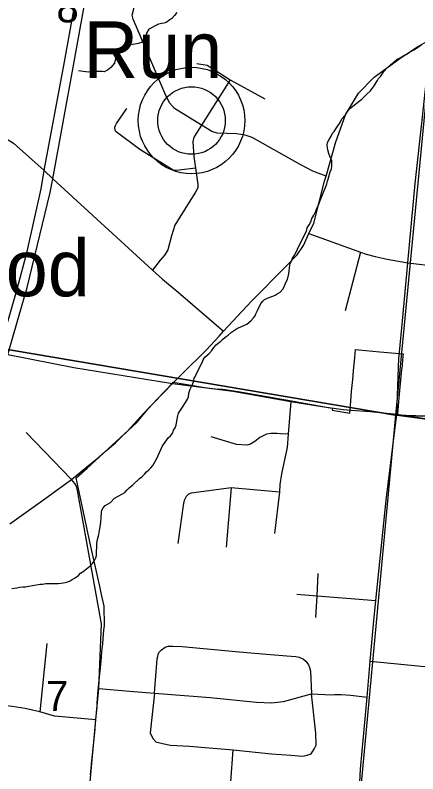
# Model space of a CAD drawing. Extents: x 0 to 34, y -3.9 to 26.2.
# Drawn here: x 7.442 to 8.005, y 17.265 to 18.325 of the extents above; entities that cross this region are included whole.
import ezdxf

# ---------------------------------------------------------------- set-up
doc = ezdxf.new("R2010")
doc.units = 0
for name, color, linetype in [('GM_X_City_Street', 7, 'Continuous'), ('GM_X_Corporation', 7, 'Continuous'), ('GM_X_County_Road', 7, 'Continuous'), ('GM_X_Interstate_Route', 7, 'Continuous'), ('GM_X_Minor_River', 7, 'Continuous'), ('GM_X_Section', 7, 'Continuous'), ('GM_X_Section_Text', 7, 'Continuous'), ('GM_X_State_Route', 7, 'Continuous'), ('GM_X_State_Shield', 7, 'Continuous'), ('GM_X_Township_Road', 7, 'Continuous'), ('GM_X_Unincorporated', 7, 'Continuous'), ('GM_X_Unincorporated_Location', 7, 'Continuous'), ('GM_X_Unincorporated_Text', 7, 'Continuous'), ('GM_X_US_Route', 7, 'Continuous')]:
    doc.layers.add(name, color=color, linetype=linetype)

msp = doc.modelspace()

# ---------------------------------------------------------------- linework, layer by layer
at = {"layer": 'GM_X_City_Street'}
msp.add_line((7.7437, 17.6648), (7.7369, 17.5816), dxfattribs=at)
for points in [[(7.827, 17.7854), (7.8234, 17.7394), (7.822, 17.7211), (7.8174, 17.6995), (7.814, 17.6842), (7.8119, 17.6693), (7.8113, 17.6586), (7.8045, 17.6009)], [(7.8234, 17.7394), (7.8129, 17.74), (7.8078, 17.7404), (7.7994, 17.7406), (7.7934, 17.7396), (7.7839, 17.7351), (7.777, 17.7295), (7.771, 17.7256), (7.7657, 17.724), (7.7513, 17.7252), (7.7161, 17.7359)], [(7.8113, 17.6586), (7.7437, 17.6648), (7.6916, 17.6576), (7.688, 17.6573), (7.6843, 17.6557), (7.6811, 17.6523), (7.6789, 17.6479), (7.6775, 17.6431), (7.6693, 17.5867)], [(7.8621, 17.4836), (7.8638, 17.5138), (7.8655, 17.5448)], [(7.8357, 17.5161), (7.8638, 17.5138), (7.946, 17.5071)], [(7.637, 17.3777), (7.6405, 17.4259), (7.6413, 17.4289), (7.6419, 17.4316), (7.6428, 17.4348), (7.6467, 17.4383), (7.6515, 17.4419), (7.6559, 17.4435), (7.6625, 17.4436), (7.6752, 17.4429), (7.7552, 17.4353), (7.7932, 17.4324), (7.8214, 17.4299), (7.834, 17.4288), (7.8388, 17.4279), (7.8447, 17.4251), (7.8487, 17.4219), (7.8519, 17.4176), (7.8533, 17.4138), (7.8547, 17.4083), (7.856, 17.3767)], [(7.9381, 17.4226), (8.0237, 17.4142), (8.239, 17.3932)], [(7.5589, 17.3845), (7.6023, 17.3808), (7.637, 17.3777), (7.7144, 17.3716), (7.7792, 17.3654), (7.8002, 17.3644), (7.8168, 17.3662), (7.856, 17.3767), (7.884, 17.3756), (7.8884, 17.376), (7.8973, 17.3761), (7.911, 17.3751), (7.9336, 17.3721)], [(7.637, 17.3777), (7.6306, 17.3225), (7.6344, 17.3143), (7.6388, 17.31), (7.648, 17.3075), (7.6593, 17.3054), (7.6858, 17.3037), (7.7133, 17.3016), (7.7466, 17.2988), (7.8001, 17.2932), (7.827, 17.2911), (7.8385, 17.2901), (7.8438, 17.2899), (7.8502, 17.2911), (7.8555, 17.293), (7.8604, 17.3004), (7.8624, 17.305), (7.8621, 17.3221), (7.856, 17.3767)], [(7.7402, 17.2146), (7.7434, 17.2541), (7.7466, 17.2988)]]:
    msp.add_lwpolyline(points, dxfattribs=at)
at = {"layer": 'GM_X_Corporation'}
msp.add_lwpolyline([(7.5475, 17.2635), (7.5488, 17.2774), (7.549, 17.2791), (7.5503, 17.2916), (7.5508, 17.2961), (7.5529, 17.3185), (7.5537, 17.3277), (7.5546, 17.3374), (7.5565, 17.3581), (7.5565, 17.3641), (7.5582, 17.382), (7.5599, 17.4), (7.5608, 17.4091), (7.5616, 17.4179), (7.5626, 17.428), (7.5633, 17.4358), (7.5644, 17.4468), (7.565, 17.4537), (7.5662, 17.4657), (7.5668, 17.4722), (7.5665, 17.4995), (7.564, 17.5095), (7.5626, 17.5156), (7.5608, 17.5247), (7.5482, 17.581), (7.5456, 17.5933), (7.5358, 17.6394), (7.5275, 17.6784), (7.5429, 17.6921), (7.6119, 17.756), (7.6249, 17.7718), (7.628, 17.7751), (7.6409, 17.7887), (7.6617, 17.8108), (7.663, 17.8122), (7.6825, 17.8088), (7.6985, 17.8061), (7.7068, 17.8048), (7.7214, 17.803), (7.7321, 17.8023), (7.7537, 17.799), (7.8203, 17.7875), (7.8821, 17.7764), (7.8853, 17.776), (7.885, 17.773), (7.9094, 17.7687), (7.9099, 17.7739), (7.9099, 17.7742), (7.9103, 17.779), (7.9121, 17.7992), (7.9137, 17.8161), (7.9147, 17.8281), (7.9152, 17.8331), (7.9159, 17.8415), (7.9164, 17.8466), (7.9174, 17.8576), (7.9221, 17.8572), (7.9513, 17.8546), (7.984, 17.8517), (7.9837, 17.8482), (7.9826, 17.837), (7.9825, 17.8353), (7.9819, 17.8294), (7.9815, 17.8256), (7.9782, 17.7901), (7.9772, 17.7791), (7.9765, 17.7726), (7.9759, 17.766), (8.021, 17.76)], dxfattribs=at)
at = {"layer": 'GM_X_County_Road'}
for points in [[(7.9788, 17.8539), (7.983, 17.8977), (7.9905, 17.9789), (8.0009, 18.0897), (8.011, 18.1822), (8.0229, 18.2914)], [(7.0486, 18.2243), (7.1006, 18.2163), (7.2883, 18.1834), (7.4286, 18.153), (7.4399, 18.1462), (7.4829, 18.1076), (7.495, 18.096), (7.634, 17.9684), (7.6481, 17.9562), (7.6699, 17.938), (7.7331, 17.8832)], [(7.8525, 18.0197), (7.9245, 17.9939), (7.9325, 17.9911)], [(7.9325, 17.9911), (7.9449, 17.9877), (7.9618, 17.9841), (7.9905, 17.9789)], [(7.9905, 17.9789), (8.1044, 17.9654), (8.1565, 17.9606), (8.2844, 17.9546), (8.3339, 17.955), (8.3899, 17.9475)], [(7.3098, 17.8727), (7.3293, 17.8691), (7.419, 17.8531), (7.4318, 17.8508), (7.5243, 17.8328), (7.6618, 17.8102)], [(7.975, 17.7675), (7.978, 17.8451), (7.9788, 17.8539)], [(7.6618, 17.8102), (7.7461, 17.7994), (7.827, 17.7854), (7.8704, 17.778), (7.9005, 17.7738), (7.9113, 17.773)], [(7.9113, 17.773), (7.9382, 17.7711), (7.975, 17.7675)], [(7.8851, 16.8268), (7.8986, 16.9786), (7.9171, 17.1239), (7.9246, 17.2715), (7.9336, 17.3721), (7.9381, 17.4226), (7.9427, 17.4741), (7.946, 17.5071), (7.9602, 17.6472), (7.975, 17.7675)], [(7.975, 17.7675), (8.0174, 17.7608), (8.0524, 17.7588)], [(7.5082, 16.8614), (7.5378, 17.1518), (7.5548, 17.3404), (7.5589, 17.3845), (7.5629, 17.4748), (7.529, 17.6609), (7.5278, 17.6669), (7.5253, 17.6705), (7.5208, 17.6763)]]:
    msp.add_lwpolyline(points, dxfattribs=at)
at = {"layer": 'GM_X_Interstate_Route'}
for points in [[(7.1816, 17.2639), (7.1949, 17.2865), (7.2068, 17.3096), (7.224, 17.3495), (7.2444, 17.3998), (7.257, 17.432), (7.2987, 17.5353), (7.3105, 17.5624), (7.3296, 17.6124), (7.3475, 17.6563), (7.3658, 17.7024), (7.3977, 17.7884), (7.419, 17.8531), (7.445, 17.9422), (7.4588, 17.9949), (7.4784, 18.0821), (7.4829, 18.1076), (7.5111, 18.2597), (7.5574, 18.5181)], [(7.3104, 17.5296), (7.316, 17.5436), (7.3414, 17.6042), (7.3602, 17.6512), (7.3786, 17.6972), (7.4104, 17.7832), (7.4318, 17.8508), (7.4589, 17.9442), (7.4912, 18.0769), (7.495, 18.096), (7.5238, 18.2545), (7.5701, 18.5129)]]:
    msp.add_lwpolyline(points, dxfattribs=at)
at = {"layer": 'GM_X_Minor_River'}
for points in [[(7.668, 18.3286), (7.6648, 18.3241), (7.6608, 18.3201), (7.658, 18.3183), (7.6529, 18.3147), (7.6498, 18.3137), (7.6471, 18.313), (7.6425, 18.3121), (7.6288, 18.305), (7.6255, 18.2998), (7.625, 18.2972), (7.6242, 18.2946), (7.6205, 18.2898), (7.6185, 18.2868), (7.6138, 18.2851), (7.6092, 18.2845), (7.6027, 18.2833), (7.5969, 18.2816), (7.593, 18.2795), (7.5881, 18.2717), (7.5824, 18.2639), (7.581, 18.2575), (7.5758, 18.2516), (7.571, 18.248), (7.5667, 18.2455), (7.5641, 18.246), (7.5599, 18.2462), (7.5553, 18.246), (7.5506, 18.2454), (7.5476, 18.2455), (7.5441, 18.2453), (7.5339, 18.2464), (7.5308, 18.2469)], [(7.7774, 17.9047), (7.7783, 17.9077), (7.7808, 17.9122), (7.7854, 17.9219), (7.7882, 17.9252), (7.7902, 17.9278), (7.7953, 17.9298), (7.8019, 17.9322), (7.8054, 17.9336), (7.8081, 17.9354), (7.8121, 17.9379), (7.8161, 17.9423), (7.8177, 17.9453), (7.8199, 17.9505), (7.8227, 17.9554), (7.8241, 17.9614), (7.8247, 17.9667), (7.8254, 17.9724), (7.8263, 17.9777), (7.828, 17.981), (7.8293, 17.9852), (7.8326, 17.99), (7.8367, 17.9978), (7.8413, 18.0075), (7.8447, 18.0146), (7.8468, 18.0191), (7.8489, 18.0232), (7.8502, 18.0277), (7.8527, 18.0318), (7.8551, 18.0362), (7.8565, 18.0407), (7.8593, 18.0456), (7.8623, 18.0512), (7.864, 18.056), (7.866, 18.0594), (7.8673, 18.0635), (7.8699, 18.0706), (7.8729, 18.0774), (7.8755, 18.0841), (7.8776, 18.0893), (7.8785, 18.0931), (7.8794, 18.0957), (7.8812, 18.1029), (7.8821, 18.1059), (7.8838, 18.11), (7.8843, 18.1138), (7.8845, 18.1176), (7.8843, 18.1218), (7.8822, 18.1264), (7.8801, 18.1315), (7.8788, 18.1368), (7.8785, 18.1395), (7.8779, 18.1433), (7.8784, 18.1467), (7.8801, 18.1501), (7.8834, 18.1557), (7.8855, 18.1598), (7.8875, 18.1624), (7.8908, 18.1676), (7.894, 18.172), (7.8965, 18.1757), (7.8985, 18.1798), (7.903, 18.1853), (7.9046, 18.1879), (7.9066, 18.1909), (7.9098, 18.1942), (7.9158, 18.1993), (7.9209, 18.2032), (7.9264, 18.2076), (7.9312, 18.212), (7.934, 18.2149), (7.938, 18.2185), (7.9408, 18.2222), (7.9425, 18.2248), (7.9449, 18.2282), (7.9465, 18.2308), (7.9482, 18.2337), (7.9498, 18.2363), (7.9522, 18.2393), (7.9571, 18.2459), (7.9623, 18.2518), (7.9663, 18.2555), (7.9714, 18.2598), (7.9758, 18.2631), (7.9797, 18.2652), (7.984, 18.2681), (7.9887, 18.2705), (7.9926, 18.2727), (7.9957, 18.2744), (7.9989, 18.2762), (8.004, 18.2798), (8.0095, 18.2834)], [(7.4444, 17.5247), (7.4487, 17.5257), (7.4529, 17.5263), (7.4567, 17.5265), (7.4613, 17.5271), (7.4664, 17.528), (7.4771, 17.5299), (7.4802, 17.5301), (7.4848, 17.5311), (7.4921, 17.5308), (7.502, 17.5312), (7.5066, 17.5313), (7.512, 17.5323), (7.5159, 17.5333), (7.519, 17.5347), (7.5218, 17.5365), (7.5249, 17.5386), (7.5304, 17.5422), (7.5332, 17.5455), (7.5371, 17.5476), (7.5466, 17.5552), (7.5502, 17.5589), (7.5531, 17.5633), (7.5547, 17.5667), (7.5556, 17.5701), (7.5564, 17.5872), (7.5573, 17.5925), (7.5588, 17.5992), (7.5598, 17.6049), (7.5607, 17.6102), (7.5618, 17.6166), (7.5624, 17.6231), (7.5627, 17.6303), (7.5632, 17.6333), (7.5653, 17.6366), (7.5681, 17.6399), (7.5751, 17.6442), (7.5807, 17.6501), (7.5921, 17.6561), (7.5952, 17.6583), (7.598, 17.6612), (7.6016, 17.6645), (7.6064, 17.6688), (7.6159, 17.6776), (7.6191, 17.6801), (7.6227, 17.6838), (7.6255, 17.6871), (7.629, 17.6896), (7.6318, 17.6926), (7.6346, 17.6959), (7.64, 17.7055), (7.6417, 17.7097), (7.6438, 17.7138), (7.6463, 17.719), (7.6476, 17.7224), (7.6492, 17.725), (7.6541, 17.7316), (7.6557, 17.7346), (7.6593, 17.7371), (7.6625, 17.7415), (7.6634, 17.7453), (7.6658, 17.7482), (7.6668, 17.752), (7.6673, 17.7554), (7.6683, 17.7607), (7.6692, 17.7652), (7.6705, 17.769), (7.6758, 17.7771), (7.6799, 17.7838), (7.6828, 17.7883), (7.6841, 17.7916), (7.6847, 17.7966), (7.6864, 17.8026), (7.6898, 17.8089), (7.6915, 17.8142), (7.6924, 17.8176), (7.6941, 17.8205), (7.695, 17.8235), (7.6978, 17.8287), (7.7016, 17.8362), (7.7037, 17.8407), (7.7049, 17.8433), (7.707, 17.847), (7.7133, 17.8521), (7.717, 17.8565), (7.7198, 17.8606), (7.723, 17.8643), (7.7258, 17.8668), (7.7293, 17.8693), (7.7317, 17.8719), (7.7353, 17.8748), (7.7396, 17.878), (7.7444, 17.882), (7.7487, 17.8849), (7.7526, 17.8874), (7.7565, 17.8892), (7.7616, 17.8912), (7.7659, 17.893), (7.7714, 17.8977), (7.775, 17.9021), (7.7774, 17.9047)], [(7.4375, 17.5242), (7.4444, 17.5247)]]:
    msp.add_lwpolyline(points, dxfattribs=at)
at = {"layer": 'GM_X_Section'}
for points in [[(7.1209, 18.9374), (8.0693, 18.7631), (7.9734, 17.7662), (7.0185, 17.9275)], [(7.0185, 17.9275), (7.9734, 17.7662), (7.8864, 16.832), (6.9147, 16.9222)]]:
    msp.add_lwpolyline(points, close=True, dxfattribs=at)
at = {"layer": 'GM_X_State_Route'}
for p, q in [((7.7269, 17.8765), (7.7331, 17.8832)), ((7.6618, 17.8102), (7.675, 17.8234)), ((7.5208, 17.6763), (7.5445, 17.6956)), ((7.4349, 17.6144), (7.4867, 17.6516))]:
    msp.add_line(p, q, dxfattribs=at)
for points in [[(7.8763, 18.0998), (7.8898, 18.1477), (7.9034, 18.1855), (7.9215, 18.2159), (7.9434, 18.2384), (7.9795, 18.2641), (8.003, 18.2802), (8.0229, 18.2914)], [(7.8525, 18.0197), (7.8595, 18.0342), (7.8744, 18.0929), (7.8763, 18.0998)], [(7.7331, 17.8832), (7.7721, 17.9253), (7.821, 17.9748), (7.8358, 17.9901), (7.8447, 18.003), (7.8525, 18.0197)], [(7.675, 17.8234), (7.7093, 17.8575), (7.7269, 17.8765)], [(7.5912, 17.7361), (7.5987, 17.7433), (7.6219, 17.7689), (7.6618, 17.8102)], [(7.5681, 17.7153), (7.5822, 17.7275), (7.5912, 17.7361)], [(7.5445, 17.6956), (7.5556, 17.7046), (7.5681, 17.7153)], [(7.4867, 17.6516), (7.5143, 17.6714), (7.5208, 17.6763)]]:
    msp.add_lwpolyline(points, dxfattribs=at)
at = {"layer": 'GM_X_State_Shield'}
for points in [[(8.9, 17.736), (8.9, 18.8013), (8.0693, 18.7631), (7.9734, 17.7662)], [(8.9, 16.9823), (8.9, 17.736), (7.9734, 17.7662), (7.8864, 16.832), (8.8743, 16.7258)]]:
    msp.add_lwpolyline(points, close=True, dxfattribs=at)
at = {"layer": 'GM_X_Township_Road'}
for p, q in [((7.9245, 17.9939), (7.9031, 17.9116)), ((7.5208, 17.6763), (7.4577, 17.7418)), ((7.4866, 17.4472), (7.4767, 17.3516))]:
    msp.add_line(p, q, dxfattribs=at)
for points in [[(7.8763, 18.0998), (7.8577, 18.1067), (7.84, 18.1163), (7.7733, 18.1537), (7.7632, 18.1572), (7.7515, 18.1592), (7.7245, 18.16), (7.7169, 18.1623), (7.7023, 18.1711), (7.6648, 18.1944), (7.6577, 18.2022), (7.6514, 18.2159), (7.6071, 18.319), (7.6058, 18.3248), (7.6079, 18.3338), (7.6215, 18.4084), (7.6342, 18.4777), (7.6432, 18.5268), (7.6442, 18.5297), (7.6458, 18.532), (7.6479, 18.5336), (7.6835, 18.546)], [(7.6959, 18.2571), (7.7101, 18.2548), (7.7217, 18.248), (7.7424, 18.2346), (7.7907, 18.208)], [(7.7424, 18.2346), (7.7023, 18.1711), (7.6925, 18.156), (7.6911, 18.1523), (7.6905, 18.148), (7.6916, 18.1275), (7.6939, 18.1112), (7.6972, 18.0882), (7.6973, 18.0856), (7.6971, 18.0836), (7.6942, 18.0776), (7.6852, 18.0634), (7.6652, 18.0314), (7.6604, 18.0167), (7.6555, 17.997), (7.6512, 17.9898), (7.6446, 17.9827), (7.634, 17.9684)], [(7.6939, 18.1112), (7.6674, 18.1078), (7.6628, 18.1082), (7.6162, 18.1372), (7.5834, 18.162), (7.5825, 18.1629), (7.5817, 18.165), (7.5815, 18.1675), (7.5816, 18.1684), (7.5822, 18.1707), (7.5838, 18.1735), (7.5983, 18.1945)], [(7.5548, 17.3404), (7.4973, 17.3457), (7.4767, 17.3516), (7.4563, 17.3564), (7.4378, 17.359), (7.4127, 17.362), (7.4054, 17.3627)]]:
    msp.add_lwpolyline(points, dxfattribs=at)
at = {"layer": 'GM_X_Unincorporated'}
for radius in [0.0744, 0.0472]:
    msp.add_circle((7.6885, 18.1776), radius, dxfattribs=at)
at = {"layer": 'GM_X_Unincorporated_Location'}
msp.add_line((7.6885, 18.1776), (7.6885, 18.1776), dxfattribs=at)
at = {"layer": 'GM_X_US_Route'}
for p, q in [((7.7269, 17.8765), (7.7331, 17.8832)), ((7.6618, 17.8102), (7.675, 17.8234)), ((7.5208, 17.6763), (7.5445, 17.6956)), ((7.4349, 17.6144), (7.4867, 17.6516))]:
    msp.add_line(p, q, dxfattribs=at)
for points in [[(7.8763, 18.0998), (7.8898, 18.1477), (7.9034, 18.1855), (7.9215, 18.2159), (7.9434, 18.2384), (7.9795, 18.2641), (8.003, 18.2802), (8.0229, 18.2914)], [(7.8525, 18.0197), (7.8595, 18.0342), (7.8744, 18.0929), (7.8763, 18.0998)], [(7.7331, 17.8832), (7.7721, 17.9253), (7.821, 17.9748), (7.8358, 17.9901), (7.8447, 18.003), (7.8525, 18.0197)], [(7.675, 17.8234), (7.7093, 17.8575), (7.7269, 17.8765)], [(7.5912, 17.7361), (7.5987, 17.7433), (7.6219, 17.7689), (7.6618, 17.8102)], [(7.5681, 17.7153), (7.5822, 17.7275), (7.5912, 17.7361)], [(7.5445, 17.6956), (7.5556, 17.7046), (7.5681, 17.7153)], [(7.4867, 17.6516), (7.5143, 17.6714), (7.5208, 17.6763)]]:
    msp.add_lwpolyline(points, dxfattribs=at)

# ---------------------------------------------------------------- texts
at = {"layer": 'GM_X_Section_Text'}
for s, p in [('8', (7.4998, 18.3147)), ('7', (7.4852, 17.3531))]:
    msp.add_text(s, height=0.0419, rotation=0, dxfattribs=at).set_placement(p)
at = {"layer": 'GM_X_Unincorporated_Text'}
for s, p in [('Run', (7.5377, 18.2371)), ('Kenwood', (7.106, 17.9321))]:
    msp.add_text(s, height=0.07898, rotation=0, dxfattribs=at).set_placement(p)

doc.saveas('drawing.dxf')
